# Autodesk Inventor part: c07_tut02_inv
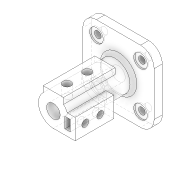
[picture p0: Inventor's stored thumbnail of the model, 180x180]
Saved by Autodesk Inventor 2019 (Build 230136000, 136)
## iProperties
Created: 2017-04
Part Number: c07_tut02_inv
Material: Generic
Document SubType Name: Modeling
Designer: CADCIM 00
Density: 1 g/cm^3
Appearance: Default
Author: CADCIM 00
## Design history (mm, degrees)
sketch "Sketch1"
  geometry: L1 (-32.5, -52.5)-(32.5, -52.5); L2 (52.5, -32.5)-(52.5, 32.5); L3 (32.5, 52.5)-(-32.5, 52.5); L4 (-52.5, 32.5)-(-52.5, -32.5); L5 (-52.5, -52.5)-(52.5, 52.5); L6 (52.5, -52.5)-(-52.5, 52.5); A1 r 20 centre (32.5, 32.5) between (52.5, 32.5) and (32.5, 52.5); A2 r 20 centre (-32.5, 32.5) between (-32.5, 52.5) and (-52.5, 32.5); A3 r 20 centre (-32.5, -32.5) between (-52.5, -32.5) and (-32.5, -52.5); A4 r 20 centre (32.5, -32.5) between (32.5, -52.5) and (52.5, -32.5); 1 further point
  constraints: 12 end point, 8 point on circle, 8 point on line, 8 tangent, 4 centre point, 3 equal radius, 2 midpoint, 2 parallel, 2 perpendicular, 1 horizontal
  dimensions: "d0" = 105 distance of L5.end L6.end; "d1" = 20 radius of A1
extrude "Extrusion1" new body sketch "Sketch1" distance "d2" = 12; taper "d3" = 0 deg
sketch "Sketch10"
  geometry: A1 r 20 centre (32.5, 32.5) between (52.5, 32.5) and (32.5, 52.5) reference; 1 further point
  constraints: 1 coincident
hole "Hole1" sketch "Sketch10" at (32.5, 32.5) diameter "d6" = 10; stored, may be unused: countersink angle "d10" = 90 deg, drill point angle "d12" = 118 deg; dims "d7" = 6, "d8" = 20, "d9" = 2, "d11" = 8
hole "Hole2" diameter "d15" = 10; stored, may be unused: countersink angle "d19" = 90 deg, drill point angle "d21" = 118 deg; dims "d13" = 10, "d14" = 10, "d16" = 6, "d17" = 20, "d18" = 2, "d20" = 8
hole "Hole3" diameter "d24" = 10; stored, may be unused: countersink angle "d28" = 90 deg, drill point angle "d30" = 118 deg; dims "d22" = 10, "d23" = 10, "d25" = 6, "d26" = 20, "d27" = 2, "d29" = 8
hole "Hole4" diameter "d33" = 10; stored, may be unused: countersink angle "d37" = 90 deg, drill point angle "d39" = 118 deg; dims "d31" = 10, "d32" = 10, "d34" = 6, "d35" = 20, "d36" = 2, "d38" = 8
sketch "Sketch2"
  geometry: C1 r 22 at (0, 0); 1 further point
  constraints: 1 centre point, 1 coincident
  dimensions: "d40" = 44 diameter of C1
extrude "Extrusion2" join sketch "Sketch2" distance "d41" = 96; taper "d42" = 0 deg
sketch "Sketch3"
  geometry: L1 (-15, 25)-(15, 25); L2 (15, 25)-(15, 16.093); L3 (-15, 16.093)-(-15, 25); L4 (0, 0)-(0, 59.776); A1 r 22 centre (0, 0) between (-15, 16.093) and (15, 16.093) reference; 1 further point
  constraints: 8 end point, 2 point on circle, 1 horizontal, 1 parallel, 1 perpendicular, 1 vertical, 1 other
  dimensions: "d43" = 30 distance between parallel lines of L2 L3; "d44" = 25 distance from line of L1 point (0, 0)
extrude "Extrusion3" join sketch "Sketch3" distance "d45" = 76; taper "d46" = 0 deg
sketch "Sketch4"
  geometry: L1 (32, 8)-(20.494, 8); L2 (32, -22)-(32, 8); L3 (0, 0)-(52.5, 0); L4 (52.5, -32.5)-(52.5, 32.5) reference; L5 (0, -22)-(32, -22); A1 r 22 centre (0, 0) between (-15, 16.093) and (15, 16.093) reference; 1 further point
  constraints: 8 end point, 3 horizontal, 2 point on circle, 1 midpoint, 1 tangent, 1 vertical
  dimensions: "d47" = 30 distance of L2.start L1.start; "d48" = 32 distance from line of point (0, 0) L2
extrude "Extrusion4" join sketch "Sketch4" distance "d49" = 57; taper "d50" = 0 deg
sketch "Sketch6"
  geometry: L1 (25, 2)-(17, 2); L2 (17, 2)-(17, -14); L3 (17, -14)-(25, -14); L4 (25, -14)-(25, 2); L5 (0, 0)-(52.778, 0)
  constraints: 10 end point, 2 horizontal, 2 parallel, 1 perpendicular
  dimensions: "d51" = 8 distance of L1.start L1.end; "d52" = 16 distance of L3.end L1.start; "d53" = 25 distance from line of L4 L5.start; "d72" = 2 distance between parallel lines of L1 L5
extrude "Extrusion5" cut sketch "Sketch6" distance "d54" = 50; taper "d55" = 0 deg
sketch "Sketch7"
  geometry: C1 r 10 at (0, 0); 1 further point
  constraints: 1 centre point, 1 coincident
  dimensions: "d56" = 20 diameter of C1
extrude "Extrusion6" cut sketch "Sketch7" stored distance "d57" = 57; taper "d58" = 0 deg
sketch "Sketch8"
  geometry: L1 (30, 0)-(0, 0) reference; L2 (0, 0)-(0, 76) reference; C1 r 6 at (15, 50); C2 r 6 at (15, 20); 1 further point
  constraints: 2 centre point, 1 equal radius, 1 vertical alignment
  dimensions: "d59" = 30 distance of C2.centre C1.centre; "d60" = 12 diameter of C1; "d61" = 20 distance from line of L1 C2.centre; "d62" = 15 distance from line of L2 C2.centre
extrude "Extrusion7" cut sketch "Sketch8" stored distance "d63" = 57; taper "d64" = 0 deg
sketch "Sketch9"
  geometry: L1 (0, 0)-(0, 57) reference; L2 (30, 0)-(0, 0) reference; C1 r 5 at (15, 15); C2 r 5 at (15, 37); 1 further point
  constraints: 2 centre point, 1 equal radius, 1 vertical alignment
  dimensions: "d65" = 10 diameter of C1; "d66" = 22 distance of C2.centre C1.centre; "d67" = 15 distance from line of L1 C1.centre; "d68" = 15 distance from line of L2 C1.centre
extrude "Extrusion8" cut sketch "Sketch9" stored distance "d69" = 57; taper "d70" = 0 deg
fillet "Fillet1" dims "d71" = 5
body "Solid1"
